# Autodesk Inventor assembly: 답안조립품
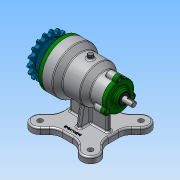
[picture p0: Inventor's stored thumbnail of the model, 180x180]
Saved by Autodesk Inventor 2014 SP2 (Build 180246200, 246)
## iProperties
Created: 2017-03
Part Number: 답안조립품
Document SubType Name: Assembly
Designer: 702
Author: 702
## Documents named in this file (14)
- C:\Users\702\Desktop\470307V1019\답안조립품.iam
- C:\Users\702\Desktop\470307V1019\본체.ipt
- C:\Users\702\Desktop\470307V1019\뒤커버.ipt
- C:\Users\702\Desktop\470307V1019\베어링-6200.ipt
- C:\Users\702\Desktop\470307V1019\베어링-6203.ipt
- C:\Users\702\Desktop\470307V1019\볼트 M4 x 12.ipt
- C:\Users\702\Desktop\470307V1019\볼트 M5 x 10.ipt
- 볼트 M5 x 10.ipt
- C:\Users\702\Desktop\470307V1019\스프로킷.ipt
- C:\Users\702\Desktop\470307V1019\앞커버.ipt
- C:\Users\702\Desktop\470307V1019\오일 실 10 20 7.ipt
- C:\Users\702\Desktop\470307V1019\오일 실 17 30 8.ipt
- C:\Users\702\Desktop\470307V1019\축.ipt
- C:\Users\702\Desktop\470307V1019\키5x5.ipt
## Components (9 placed, 1 different names)
1. ISO 4762 M4 x 12:1
2. ISO 4762 M4 x 12:3
3. ISO 4762 M4 x 12:4
4. ISO 4762 M4 x 12:5
5. ISO 4762 M4 x 12:6
6. ISO 4762 M4 x 12:7
7. ISO 4762 M4 x 12:2
8. ISO 4762 M4 x 12:8
9. ISO 4762 M4 x 12:9
